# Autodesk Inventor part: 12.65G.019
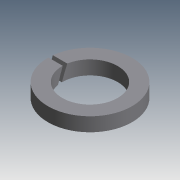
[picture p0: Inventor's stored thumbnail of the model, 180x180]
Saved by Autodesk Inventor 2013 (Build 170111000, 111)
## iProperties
Shininess: 25.0
Length Units: 11269
Angle Units: 11279
Time Units: 11290
Mass Units: 11283
Length Display Precision: 3
Angle Display Precision: 2
Created: 2001-04
Material: Steel, Mild
Document SubType Name: Modeling
Designer: tevgeniy
Mass: 3.40115 g
Surface Area: 5.87487 cm^2
Volume: 0.432716 cm^3
Density: 7.86 g/cm^3
Density: 0.0
Volumn: 0.0
Area: 0.0
PropertySet Name: Model Information
Control State: 0
Master: False
Checked Out: True
Last Check In Date: 2008-10-15
Checked Out Date: 2008-10-15
Author: tevgeniy
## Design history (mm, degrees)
node "ExtrusionBlind1" dims "d2" = 3, "d3" = 0
  sketch "Sketch1"
    geometry: C1 r 9.1 at (-266.435, -313.047)
    constraints: 1 centre point, 1 other
    dimensions: "d1" = 18.2 diameter of C1
node "Hole1" dims "d5" = 12, "d6" = 4, "d7" = 2, "d8" = 60 deg, "d9" = 8, "d10" = 118 deg
  sketch "Sketch2"
    geometry: C1 r 9.1 at (0, 0) reference
node "WorkAxis1"
workplane "Work Plane1"
workplane "Work Plane2"
node "WorkPlane1"
node "ExtrusionToFace1" dims "d18" = 0.13, "d19" = 0
  sketch "Sketch3"
    geometry: L1 (-25.913, -0.092)-(-25.913, -1); L2 (-22.913, 1)-(-25.913, -0.092); L3 (-22.913, 0.092)-(-22.913, 1); L4 (-25.913, -1)-(-22.913, 0.092); L5 (-11.456, 0)-(-37.369, 0); C1 r 9.1 at (-22.913, 0); C2 r 9.1 at (-25.913, 0)
    constraints: 10 end point, 2 centre point, 2 parallel, 1 vertical
    dimensions: "d13" = 0 horizontal distance of L2.start C1.centre; "d15" = 0 horizontal distance of L1.start C2.centre; "d17" = 160 deg angle of L4 L5
body "Solid1"
other parameters: "d0" = 18.2 (derived), "d4" = 0, "d11" = 0, "d12" = 0 (derived), "d14" = 0 (derived), "d16" = 160 deg (derived)
